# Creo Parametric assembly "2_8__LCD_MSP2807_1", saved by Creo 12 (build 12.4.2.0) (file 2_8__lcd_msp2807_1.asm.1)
Units: Custom; MM, KILOGRAM, SECS

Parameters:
  PTC_WM_ITERATION = "0"
  PTC_WM_VERSION = "-.0"
  PTC_WM_LIFECYCLE_STATE = "In Work"
  PTC_WM_LIFECYCLE = "MO_CADDocument"
  PTC_WM_CREATED_BY = "Maximilian Roepper (Z0017RMS: MO)"
  PTC_WM_CREATED_ON = "18-Sep-26 11:36:42 AM"
  PTC_WM_MODIFIED_BY = "Maximilian Roepper (Z0017RMS: MO)"
  PTC_WM_MODIFIED_ON = "18-Sep-26 11:36:46 AM"
  PDMLINKNUMBER = "PDM000071455238"
  PTC_WM_NAME = "2_8__lcd_msp2807_1.asm"
  PTC_WM_NUMBER = "PDM000071455238"

Other parameters: WEIGHT, WEIGHT_FACTOR, WEIGHT_ADD, MC_ERRORS, SUPPLIER, ISPOSITIONINGASSEMBLY

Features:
  1. coordinate system
  2. imported feature
  3. component "BOARD_1"
  4. component "DISPLAY_AND_TOUCHSCREEN_1"

Other named items: DRW_VIEW_ORG, ROUGH-GROB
